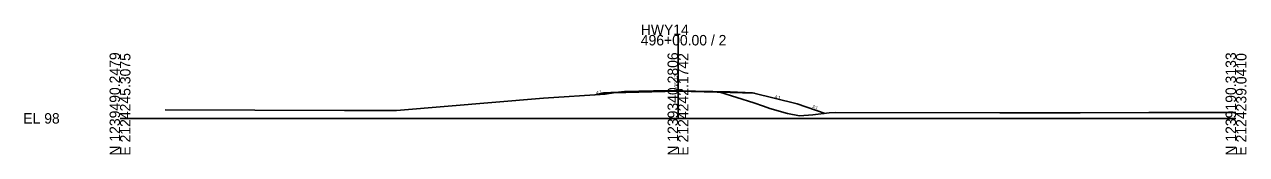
# Model space of a CAD drawing. Extents: x -26 to 303, y -10 to 11521.
# Drawn here: x -25.7 to 302.8, y 7490.3 to 7525.2 of the extents above; entities that cross this region are included whole.
import ezdxf

# ---------------------------------------------------------------- set-up
doc = ezdxf.new("R2010")
doc.units = 0
for name, color, linetype in [('XS_CELL', 7, 'Continuous'), ('XS_P_FINISHED_GRADE', 7, 'Continuous'), ('XS_P_SUBGRADE_GRANULAR', 7, 'Continuous'), ('XS_P_SUBGRADE_LEVELING', 7, 'Continuous'), ('XS_P_TX_FS_BS', 7, 'Continuous'), ('XS_X_GROUND', 7, 'Continuous'), ('XS_X_GROUND_TX', 7, 'Continuous')]:
    doc.layers.add(name, color=color, linetype=linetype)

msp = doc.modelspace()

# ---------------------------------------------------------------- linework, layer by layer
at = {"layer": 'XS_CELL'}
for p, q in [((150, 7500), (150, 7522.35)), ((0, 7500), (150, 7500)), ((150, 7500), (300, 7500))]:
    msp.add_line(p, q, dxfattribs=at)
at = {"layer": 'XS_P_FINISHED_GRADE'}
for p, q in [((136, 7507.09), (130, 7506.85)), ((150, 7507.37), (136, 7507.09)), ((150, 7507.37), (164, 7507.09)), ((164, 7507.09), (170, 7506.85)), ((130, 7506.85), (127.77, 7506.3)), ((170, 7506.85), (182, 7503.85)), ((182, 7503.85), (189.59, 7501.32))]:
    msp.add_line(p, q, dxfattribs=at)
at = {"layer": 'XS_P_SUBGRADE_GRANULAR'}
for p, q in [((136, 7506.97), (129.4, 7506.71)), ((164, 7506.97), (170.6, 7506.71))]:
    msp.add_line(p, q, dxfattribs=at)
at = {"layer": 'XS_P_SUBGRADE_LEVELING'}
for p, q in [((150, 7507.25), (136, 7506.97)), ((136, 7506.97), (136, 7507.09)), ((150, 7507.25), (164, 7506.97)), ((164, 7506.97), (164, 7507.09))]:
    msp.add_line(p, q, dxfattribs=at)
at = {"layer": 'XS_X_GROUND'}
for p, q in [((133.16, 7506.94), (135.63, 7507.15)), ((135.63, 7507.15), (147.29, 7507.45)), ((147.29, 7507.45), (150, 7507.37)), ((150, 7507.37), (157.87, 7507.15)), ((157.87, 7507.15), (161.27, 7507.02)), ((161.27, 7507.02), (170.37, 7504.17)), ((74.32, 7502.1), (113.84, 7505.45)), ((113.84, 7505.45), (130.41, 7506.46)), ((130.41, 7506.46), (133.16, 7506.94)), ((170.37, 7504.17), (173, 7503.25)), ((12.18, 7502.27), (60.34, 7502.13)), ((60.34, 7502.13), (70.93, 7502.11)), ((70.93, 7502.11), (74.32, 7502.1)), ((173, 7503.25), (174.73, 7502.61)), ((174.73, 7502.61), (179.43, 7501.27)), ((179.43, 7501.27), (182.62, 7500.64)), ((182.62, 7500.64), (186.21, 7500.96)), ((186.21, 7500.96), (190.63, 7501.44)), ((190.63, 7501.44), (192.35, 7501.6)), ((192.35, 7501.6), (236.52, 7501.43)), ((236.52, 7501.43), (258.15, 7501.47)), ((258.15, 7501.47), (276.56, 7501.55)), ((276.56, 7501.55), (299.19, 7501.56)), ((299.19, 7501.56), (300, 7501.56))]:
    msp.add_line(p, q, dxfattribs=at)

# ---------------------------------------------------------------- texts
at = {"layer": 'XS_CELL'}
for s, p in [('HWY14', (140, 7522.35)), ('496+00.00 / 2', (140, 7519.55)), ('EL 98', (-26, 7498.6))]:
    msp.add_text(s, height=2.8, dxfattribs=at).set_placement(p)
for s, p in [('N 1239490.2479', (0, 7490)), ('E 2124245.3075', (2.8, 7490)), ('N 1239340.2806', (150, 7490)), ('E 2124242.1742', (152.8, 7490)), ('N 1239190.3133', (300, 7490)), ('E 2124239.0410', (302.8, 7490))]:
    msp.add_text(s, height=2.8, rotation=90, dxfattribs=at).set_placement(p)
at = {"layer": 'XS_P_TX_FS_BS'}
for s, rotation, p in [('4:1', 14.0362, (128.09, 7506.47)), ('4:1', 345.9638, (175.95, 7505.5)), ('3:1', 341.5651, (186.02, 7502.88))]:
    msp.add_text(s, height=0.8, rotation=rotation, dxfattribs=at).set_placement(p)
at = {"layer": 'XS_X_GROUND_TX'}
msp.add_text('105.37', height=1, rotation=90, dxfattribs=at).set_placement((150, 7507.47))

doc.saveas('drawing.dxf')
